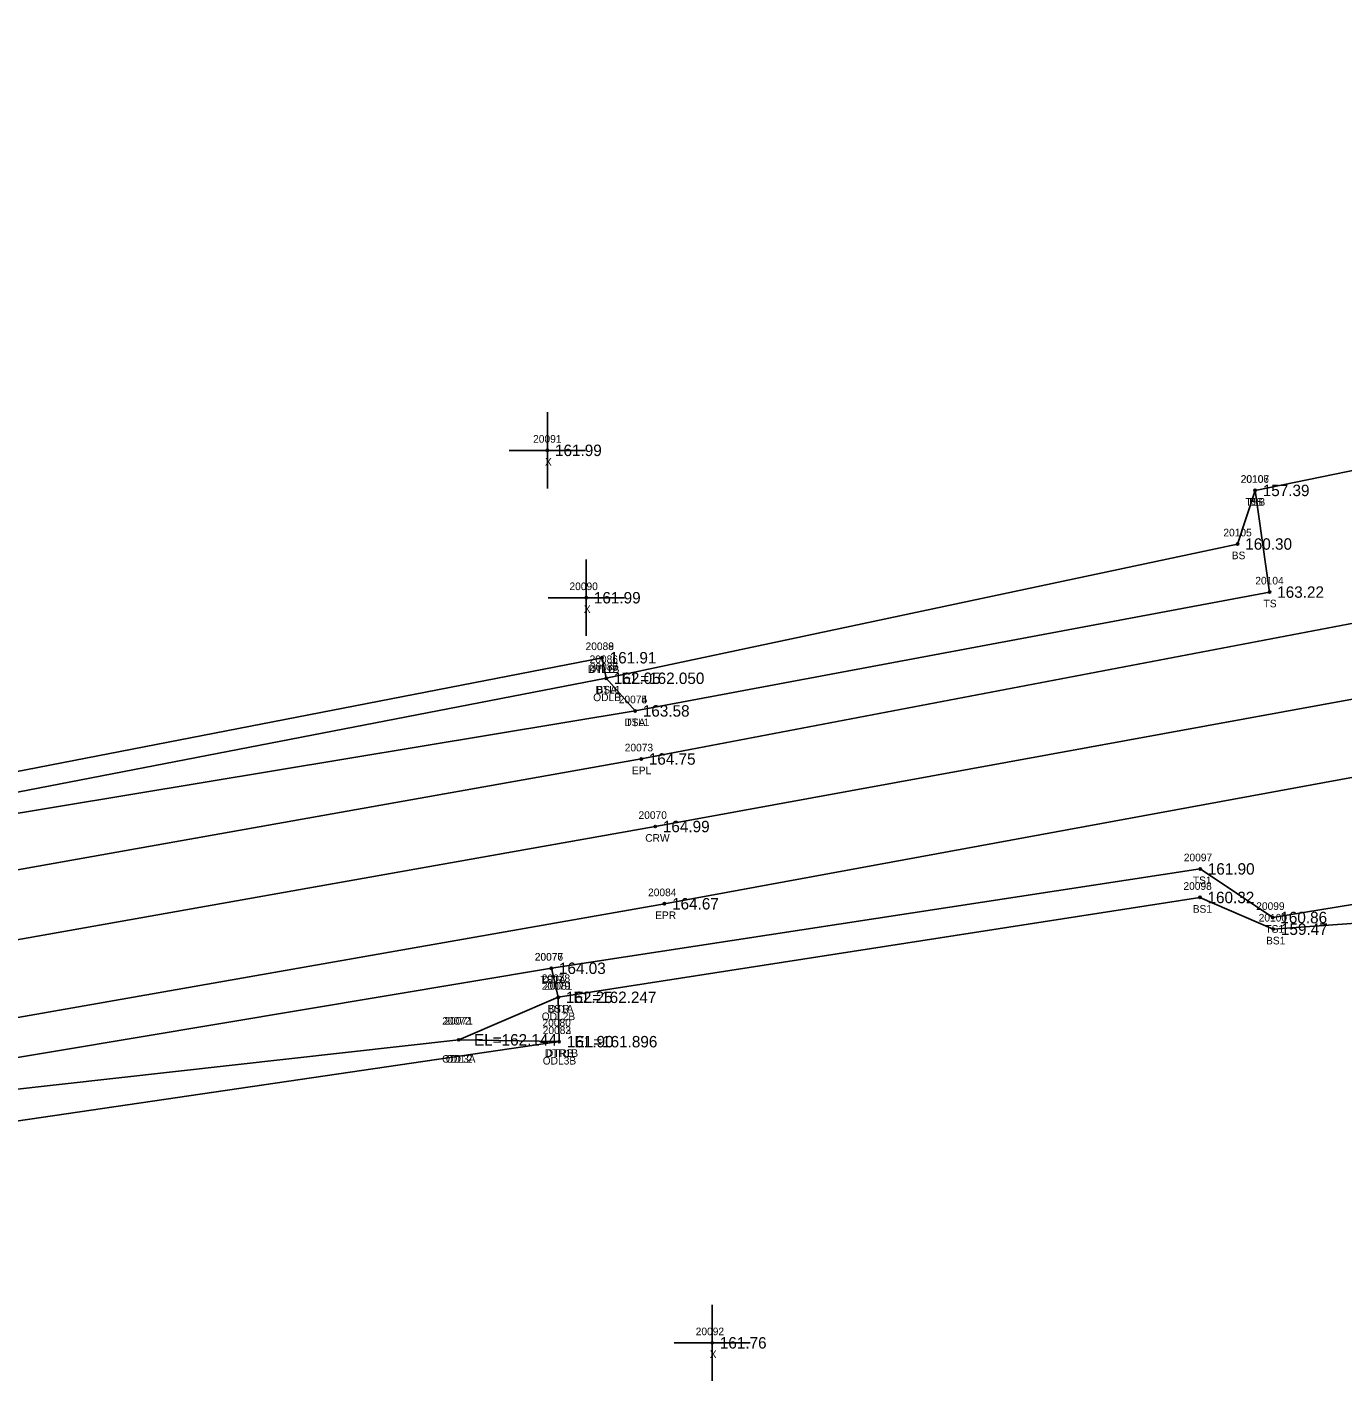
# Model space of a CAD drawing. Extents: x 2381545 to 2382928, y 1029933 to 1030589.
# Drawn here: x 2381717.1 to 2381889.7, y 1030221.7 to 1030399.4 of the extents above; entities that cross this region are included whole.
import ezdxf

# ---------------------------------------------------------------- set-up
doc = ezdxf.new("R2010")
doc.units = 0
for name, color, linetype in [('RD_DTM_BkLn1', 7, 'Continuous'), ('RD_DTM_BkLn2', 7, 'Continuous'), ('RD_DTM_BkLn_txCode', 7, 'Continuous'), ('RD_EX_H2O', 7, 'Continuous'), ('RD_EX_H2O_txCode', 7, 'Continuous'), ('RD_EX_Misc', 7, 'Continuous'), ('RD_EX_Misc_txCode', 7, 'Continuous'), ('RD_EX_Road', 7, 'Continuous'), ('RD_EX_Road_txCode', 7, 'Continuous'), ('RD_EX_TX_H2O_ELEV', 7, 'Continuous'), ('RD_EX_TX_Misc_ELEV', 7, 'Continuous'), ('RD_EX_TX_Road_ELEV', 7, 'Continuous'), ('RD_HC_Survey_ELEV', 7, 'Continuous'), ('RD_HC_Survey_txCode', 7, 'Continuous'), ('RD_SMD_Locator', 7, 'Continuous')]:
    doc.layers.add(name, color=color, linetype=linetype)

msp = doc.modelspace()

# ---------------------------------------------------------------- linework, layer by layer
at = {"layer": 'RD_DTM_BkLn1'}
msp.add_lwpolyline([(2381547.18, 1030259.1), (2381595.71, 1030262.71), (2381646.12, 1030268.56), (2381695.78, 1030276.09), (2381799.52, 1030294.49), (2381897.44, 1030312.39), (2382008.24, 1030333.66), (2382118.08, 1030354.86), (2382202.13, 1030371.04)], dxfattribs=at)
at = {"layer": 'RD_DTM_BkLn2'}
for points in [[(2381793.09, 1030313.94), (2381875.92, 1030331.56), (2381878.21, 1030338.59), (2381904.22, 1030343.93), (2381908.67, 1030338.54), (2382000.53, 1030356.42), (2382114.53, 1030387.99), (2382160.73, 1030399.39)], [(2381785.89, 1030275.89), (2381871.01, 1030288.93), (2381880.52, 1030282.55), (2381901.68, 1030286.01), (2382013.28, 1030298.25), (2382122.09, 1030316.46), (2382195.01, 1030325.62), (2382206, 1030331.71), (2382212.25, 1030344.58), (2382207.28, 1030357.44), (2382204.69, 1030361.31)], [(2381786.8, 1030272.08), (2381870.97, 1030285.18), (2381880.6, 1030281.02), (2381901.08, 1030282.53), (2382011.65, 1030292.89), (2382122.26, 1030312.46), (2382194.74, 1030319.65), (2382207.56, 1030328.92), (2382216.83, 1030343.34)], [(2381796.89, 1030309.66), (2381880.11, 1030325.25), (2381878.21, 1030338.59)]]:
    msp.add_lwpolyline(points, dxfattribs=at)
at = {"layer": 'RD_EX_H2O'}
for p, q in [((2381692.86, 1030294.53), (2381793.09, 1030313.94)), ((2381773.74, 1030266.5), (2381786.92, 1030266.26))]:
    msp.add_line(p, q, dxfattribs=at)
for points in [[(2381690.14, 1030294.24), (2381692.74, 1030292.38), (2381796.89, 1030309.66), (2381793.09, 1030313.94), (2381792.54, 1030316.64)], [(2381690.14, 1030294.24), (2381692.36, 1030297.17), (2381792.54, 1030316.64)], [(2381547.56, 1030243.37), (2381597.37, 1030247.52), (2381647.02, 1030253.93), (2381698.86, 1030261.36), (2381785.89, 1030275.89), (2381786.8, 1030272.08), (2381786.92, 1030266.26)], [(2381547.45, 1030241.73), (2381597.44, 1030245.79), (2381647.09, 1030252.51), (2381698.99, 1030258.16), (2381773.74, 1030266.5), (2381786.8, 1030272.08)], [(2381547.94, 1030234.54), (2381598.49, 1030237.78), (2381648.57, 1030245.5), (2381699.53, 1030253.48), (2381786.92, 1030266.26)]]:
    msp.add_lwpolyline(points, dxfattribs=at)
at = {"layer": 'RD_EX_Misc'}
for p, q in [((2381785.37, 1030338.85), (2381785.37, 1030348.85)), ((2381780.37, 1030343.85), (2381790.37, 1030343.85)), ((2381790.47, 1030319.51), (2381790.47, 1030329.51)), ((2381785.47, 1030324.51), (2381795.47, 1030324.51)), ((2381806.99, 1030221.74), (2381806.99, 1030231.74)), ((2381801.99, 1030226.74), (2381811.99, 1030226.74))]:
    msp.add_line(p, q, dxfattribs=at)
at = {"layer": 'RD_EX_Road'}
for points in [[(2381547.21, 1030268.01), (2381595.28, 1030271.86), (2381645.28, 1030277.12), (2381675.41, 1030281.84), (2381694.68, 1030285.03), (2381797.68, 1030303.35), (2381895.95, 1030322.08), (2382005.53, 1030342.57), (2382116.42, 1030363.72), (2382200, 1030380.28), (2382202.13, 1030371.04)], [(2381547.49, 1030248.39), (2381596.55, 1030252.33), (2381646.64, 1030258.33), (2381698.19, 1030266.34), (2381800.73, 1030284.35), (2381899.22, 1030302.47), (2382010.02, 1030323.79), (2382119.81, 1030345.41), (2382204.69, 1030361.31), (2382202.13, 1030371.04)]]:
    msp.add_lwpolyline(points, dxfattribs=at)
at = {"layer": 'RD_SMD_Locator'}
for centre in [(2381785.37, 1030343.85), (2381878.21, 1030338.59), (2381878.21, 1030338.59), (2381875.92, 1030331.56), (2381880.11, 1030325.25), (2381790.47, 1030324.51), (2381792.54, 1030316.64), (2381792.54, 1030316.64), (2381793.09, 1030313.94), (2381793.09, 1030313.94), (2381793.09, 1030313.94), (2381796.89, 1030309.66), (2381796.89, 1030309.66), (2381797.68, 1030303.35), (2381799.52, 1030294.49), (2381871.01, 1030288.93), (2381800.73, 1030284.35), (2381870.97, 1030285.18), (2381880.52, 1030282.55), (2381880.6, 1030281.02), (2381785.89, 1030275.89), (2381785.89, 1030275.89), (2381786.8, 1030272.08), (2381786.8, 1030272.08), (2381786.8, 1030272.08), (2381773.74, 1030266.5), (2381773.74, 1030266.5), (2381786.92, 1030266.26), (2381786.92, 1030266.26), (2381786.92, 1030266.26), (2381806.99, 1030226.74)]:
    msp.add_circle(centre, 0.15, dxfattribs=at)

# ---------------------------------------------------------------- texts
at = {"layer": 'RD_DTM_BkLn_txCode'}
for s, p in [('20106', (2381876.31, 1030339.59)), ('20107', (2381876.34, 1030339.59)), ('TSB', (2381876.94, 1030336.59)), ('BS', (2381877.43, 1030336.59)), ('20105', (2381874.05, 1030332.56)), ('BS', (2381875.15, 1030329.56)), ('20104', (2381878.24, 1030326.25)), ('TS', (2381879.32, 1030323.25)), ('20087', (2381790.94, 1030314.94)), ('BSA', (2381791.83, 1030311.94)), ('20075', (2381794.74, 1030310.66)), ('TSA', (2381795.61, 1030307.66)), ('20097', (2381868.86, 1030289.93)), ('TS1', (2381870.05, 1030286.93)), ('20098', (2381868.81, 1030286.18)), ('20099', (2381878.36, 1030283.55)), ('BS1', (2381870.03, 1030283.18)), ('20100', (2381878.68, 1030282.02)), ('TS1', (2381879.56, 1030280.55)), ('BS1', (2381879.65, 1030279.02)), ('20077', (2381783.73, 1030276.89)), ('TS1A', (2381784.44, 1030273.89)), ('20079', (2381784.64, 1030273.08)), ('BS1A', (2381785.37, 1030270.08))]:
    msp.add_text(s, height=1, dxfattribs=at).set_placement(p)
at = {"layer": 'RD_EX_H2O_txCode'}
for s, p in [('20088', (2381790.38, 1030317.64)), ('20089', (2381790.38, 1030317.64)), ('20086', (2381790.91, 1030315.94)), ('DTL1B', (2381790.66, 1030314.64)), ('DTLB', (2381790.83, 1030314.64)), ('20085', (2381790.94, 1030314.94)), ('DTL1', (2381791.68, 1030311.94)), ('ODLB', (2381791.38, 1030310.94)), ('20074', (2381794.74, 1030310.66)), ('DTL1', (2381795.48, 1030307.66)), ('20076', (2381783.71, 1030276.89)), ('20078', (2381784.64, 1030274.08)), ('DTR', (2381784.62, 1030273.89)), ('20081', (2381784.93, 1030273.08)), ('DTR', (2381785.53, 1030270.08)), ('20072', (2381771.58, 1030268.5)), ('20071', (2381771.86, 1030268.5)), ('ODL2B', (2381784.63, 1030269.08)), ('20080', (2381784.73, 1030268.26)), ('20082', (2381784.76, 1030267.26)), ('20083', (2381784.76, 1030267.26)), ('DTR1B', (2381785.02, 1030264.26)), ('DTRB', (2381785.18, 1030264.26)), ('ODL3A', (2381771.56, 1030263.5)), ('ODL2', (2381772.04, 1030263.5)), ('ODL3B', (2381784.76, 1030263.26))]:
    msp.add_text(s, height=1, dxfattribs=at).set_placement(p)
at = {"layer": 'RD_EX_Misc_txCode'}
for s, p in [('20091', (2381783.5, 1030344.85)), ('X', (2381785.05, 1030341.85)), ('20090', (2381788.27, 1030325.51)), ('X', (2381790.15, 1030322.51)), ('20092', (2381804.83, 1030227.74)), ('X', (2381806.67, 1030224.74))]:
    msp.add_text(s, height=1, dxfattribs=at).set_placement(p)
at = {"layer": 'RD_EX_Road_txCode'}
for s, p in [('20073', (2381795.52, 1030304.35)), ('EPL', (2381796.47, 1030301.35)), ('20084', (2381798.58, 1030285.35)), ('EPR', (2381799.51, 1030282.35))]:
    msp.add_text(s, height=1, dxfattribs=at).set_placement(p)
at = {"layer": 'RD_EX_TX_H2O_ELEV'}
for s, p in [('161.91', (2381793.54, 1030315.89)), ('161.91', (2381793.54, 1030315.89)), ('162.05', (2381794.09, 1030313.19)), ('EL=162.050', (2381795.09, 1030313.19)), ('163.58', (2381797.89, 1030308.91)), ('164.03', (2381786.89, 1030275.14)), ('162.25', (2381787.8, 1030271.33)), ('EL=162.247', (2381788.8, 1030271.33)), ('EL=162.144', (2381775.74, 1030265.75)), ('EL=162.144', (2381775.74, 1030265.75)), ('161.90', (2381787.92, 1030265.51)), ('161.90', (2381787.92, 1030265.51)), ('EL=161.896', (2381788.92, 1030265.51))]:
    msp.add_text(s, height=1.5, dxfattribs=at).set_placement(p)
at = {"layer": 'RD_EX_TX_Misc_ELEV'}
for s, p in [('161.99', (2381786.37, 1030343.1)), ('157.39', (2381879.21, 1030337.84)), ('157.39', (2381879.21, 1030337.84)), ('160.30', (2381876.92, 1030330.81)), ('161.99', (2381791.47, 1030323.76)), ('163.22', (2381881.11, 1030324.5)), ('162.05', (2381794.09, 1030313.19)), ('163.58', (2381797.89, 1030308.91)), ('161.90', (2381872.01, 1030288.18)), ('160.32', (2381871.97, 1030284.43)), ('160.86', (2381881.52, 1030281.8)), ('159.47', (2381881.6, 1030280.27)), ('164.03', (2381786.89, 1030275.14)), ('162.25', (2381787.8, 1030271.33)), ('161.76', (2381807.99, 1030225.99))]:
    msp.add_text(s, height=1.5, dxfattribs=at).set_placement(p)
at = {"layer": 'RD_EX_TX_Road_ELEV'}
for s, p in [('164.75', (2381798.68, 1030302.6)), ('164.67', (2381801.73, 1030283.6))]:
    msp.add_text(s, height=1.5, dxfattribs=at).set_placement(p)
at = {"layer": 'RD_HC_Survey_ELEV'}
msp.add_text('164.99', height=1.5, dxfattribs=at).set_placement((2381800.52, 1030293.74))
at = {"layer": 'RD_HC_Survey_txCode'}
for s, p in [('20070', (2381797.33, 1030295.49)), ('CRW', (2381798.21, 1030292.49))]:
    msp.add_text(s, height=1, dxfattribs=at).set_placement(p)

doc.saveas('drawing.dxf')
